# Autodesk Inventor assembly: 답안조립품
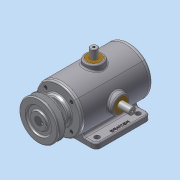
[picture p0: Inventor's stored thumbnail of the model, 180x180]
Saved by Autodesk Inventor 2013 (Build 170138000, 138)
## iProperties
Created: 2014-11
Part Number: 답안조립품
Document SubType Name: Assembly
Designer: Administrator
Mass: 3490.54 g
Surface Area: 2329.56 cm^2
Volume: 1071.41 cm^3
Density: 3.2579 g/cm^3
Author: Administrator
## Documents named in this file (15)
- C:\Users\Administrator\Desktop\341123V1025\341123V1025\답안조립품.iam
- C:\Users\Administrator\Desktop\341123V1025\341123V1025\본체.ipt
- C:\Users\Administrator\Desktop\341123V1025\341123V1025\KS B 1028  - 납작점M4x5.ipt
- C:\Users\Administrator\Desktop\341123V1025\341123V1025\KS B 1311 - 5 x 5 x 18I.ipt
- C:\Users\Administrator\Desktop\341123V1025\341123V1025\M4-소켓머리.ipt
- C:\Users\Administrator\Desktop\341123V1025\341123V1025\V-벨트풀리.ipt
- C:\Users\Administrator\Desktop\341123V1025\341123V1025\뒷커버.ipt
- C:\Users\Administrator\Desktop\341123V1025\341123V1025\베어링 6203.ipt
- C:\Users\Administrator\Desktop\341123V1025\341123V1025\부시.ipt
- C:\Users\Administrator\Desktop\341123V1025\341123V1025\스프링.ipt
- C:\Users\Administrator\Desktop\341123V1025\341123V1025\스프링2.ipt
- C:\Users\Administrator\Desktop\341123V1025\341123V1025\슬라이더.ipt
- C:\Users\Administrator\Desktop\341123V1025\341123V1025\앞커버.ipt
- C:\Users\Administrator\Desktop\341123V1025\341123V1025\오일실.ipt
- C:\Users\Administrator\Desktop\341123V1025\341123V1025\축.ipt
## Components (14 placed, 6 different names)
1. KS B 1028 납작점 - 미터 납작점M4x5:1 — 플러쉬:3
2. KS B 1311 (I) 5 x 5 x 18:1
3. V-벨트풀리:1 — 플러쉬:1
4. 7-베어링 6203:1
5. 8-오일실:1
6. 7-베어링 6203:2
7. 9-M4-소켓머리:1
8. 9-M4-소켓머리:3
9. 9-M4-소켓머리:4
10. 9-M4-소켓머리:5
11. 9-M4-소켓머리:2
12. 9-M4-소켓머리:6
13. 9-M4-소켓머리:7
14. 9-M4-소켓머리:8
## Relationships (2: Flush 2)
- 플러쉬:1 [Flush]: V-벨트풀리:1
- 플러쉬:3 [Flush]: KS B 1028 납작점 - 미터 납작점M4x5:1
